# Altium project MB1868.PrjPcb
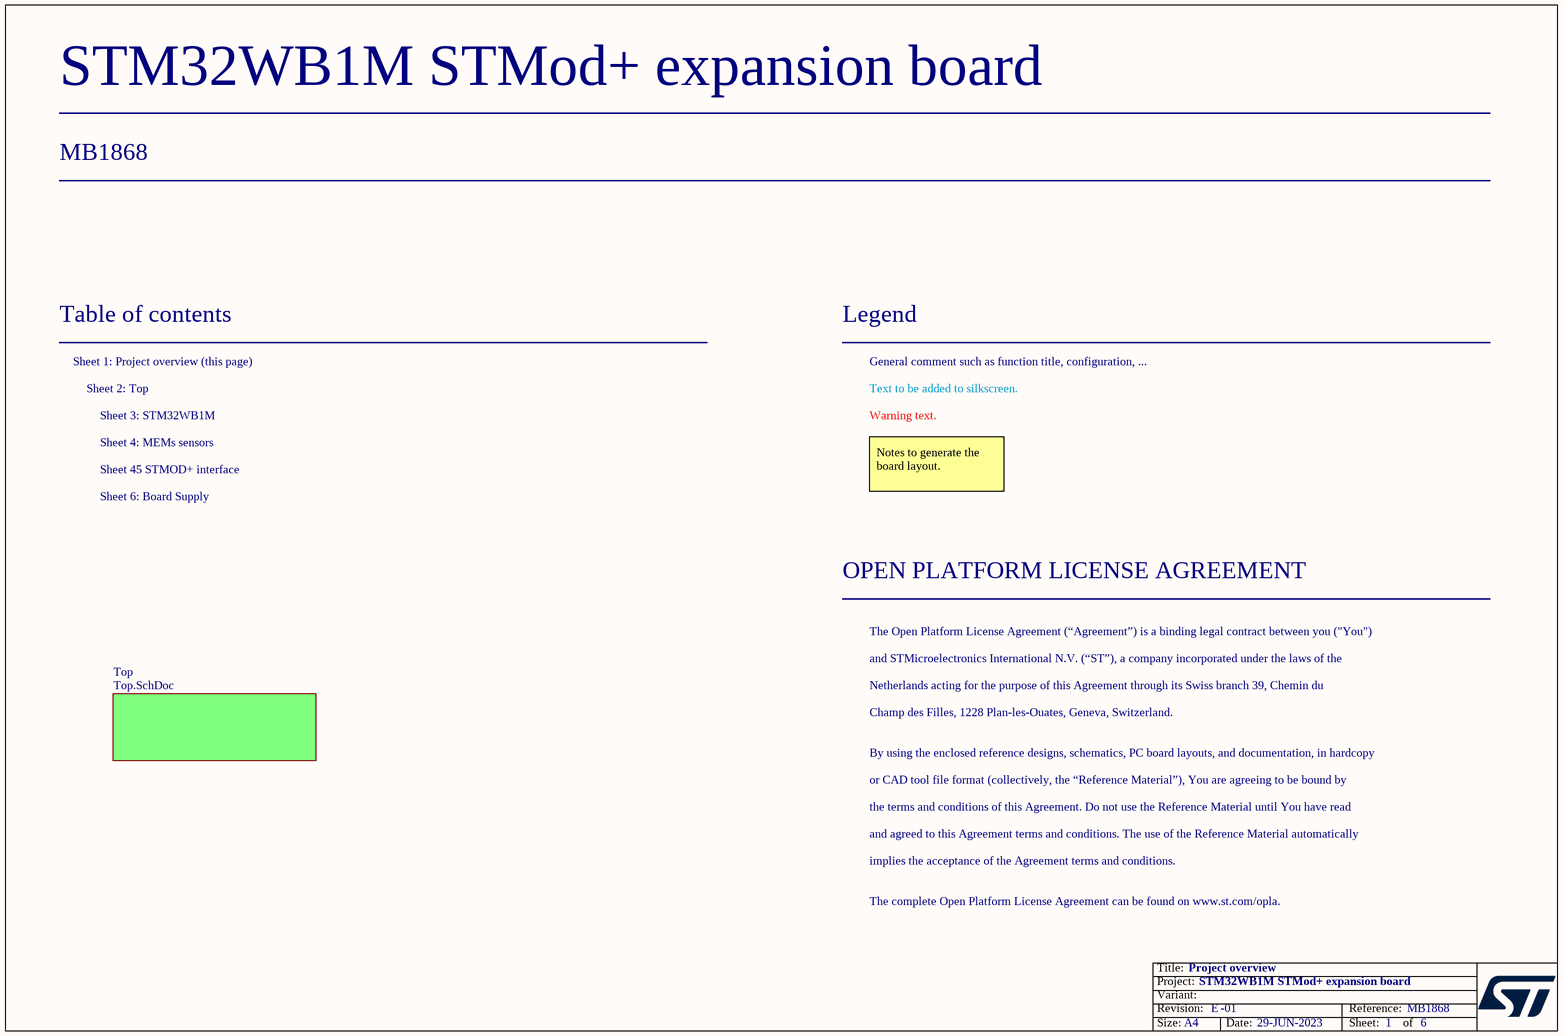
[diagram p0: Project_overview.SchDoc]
Board_Assembly_Revision: 01; Board_Document_Date: 29-JUN-2023; Board_Name: STM32WB1M STMod+ expansion board; Board_PCB_Revision: E; Board_Reference: MB1868
6 sheets, 72 parts. Net scope: flat (ports and power ports of the same name join across sheets).
Board file: MB1868.PcbDoc
Sheets:
  Project_overview.SchDoc
    Top = Top.SchDoc
      U_Mems = Mems.SchDoc
      U_STM32WB1M = STM32WB1M.SchDoc
      U_Board_supply = Board_supply.SchDoc
      U_STMOD+_interface = STMOD+_interface.SchDoc

## Sheet Project_overview.SchDoc: Project overview
size A4; Date: Not used; ApprovedBy: Not used; CheckedBy: Not used; Author: Not used; CompanyName: STMicroelectronics; DrawnBy: Not used; Engineer: Not used; Organization: Not used; Address1: Not used; Address2: Not used; Address3: Not used; Address4: Not used; DocumentNumber: Not used; Revision: Not used; SheetNumber: 1; SheetTotal: 6

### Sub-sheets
Top = Top.SchDoc: no entries

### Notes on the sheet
- Table of contents
- Sheet 1: Project overview (this page)
- Legend
- General comment such as function title, configuration, ...
- Sheet 2: Top
- Sheet 3: STM32WB1M
- Sheet 4: MEMs sensors
- Text to be added to silkscreen.
- Warning text.
- Sheet 6: Board Supply
- Sheet 45 STMOD+ interface
- Notes to generate the board layout.
- OPEN PLATFORM LICENSE AGREEMENT
- The Open Platform License Agreement (“Agreement”) is a binding legal contract between you ("You")
- and STMicroelectronics International N.V. (“ST”), a company incorporated under the laws of the
- Netherlands acting for the purpose of this Agreement through its Swiss branch 39, Chemin du
- Champ des Filles, 1228 Plan-les-Ouates, Geneva, Switzerland.
- By using the enclosed reference designs, schematics, PC board layouts, and documentation, in hardcopy
- or CAD tool file format (collectively, the “Reference Material”), You are agreeing to be bound by
- the terms and conditions of this Agreement. Do not use the Reference Material until You have read
- and agreed to this Agreement terms and conditions. The use of the Reference Material automatically
- implies the acceptance of the Agreement terms and conditions.
- The complete Open Platform License Agreement can be found on www.st.com/opla.

## Sheet Top.SchDoc: Top hierarchical view
size A4; Date: Not used; ApprovedBy: Not used; CheckedBy: Not used; Author: Not used; CompanyName: STMicroelectronics; DrawnBy: Not used; Engineer: Not used; Organization: Not used; Address1: Not used; Address2: Not used; Address3: Not used; Address4: Not used; DocumentNumber: Not used; Revision: Not used; SheetNumber: 2; SheetTotal: 6
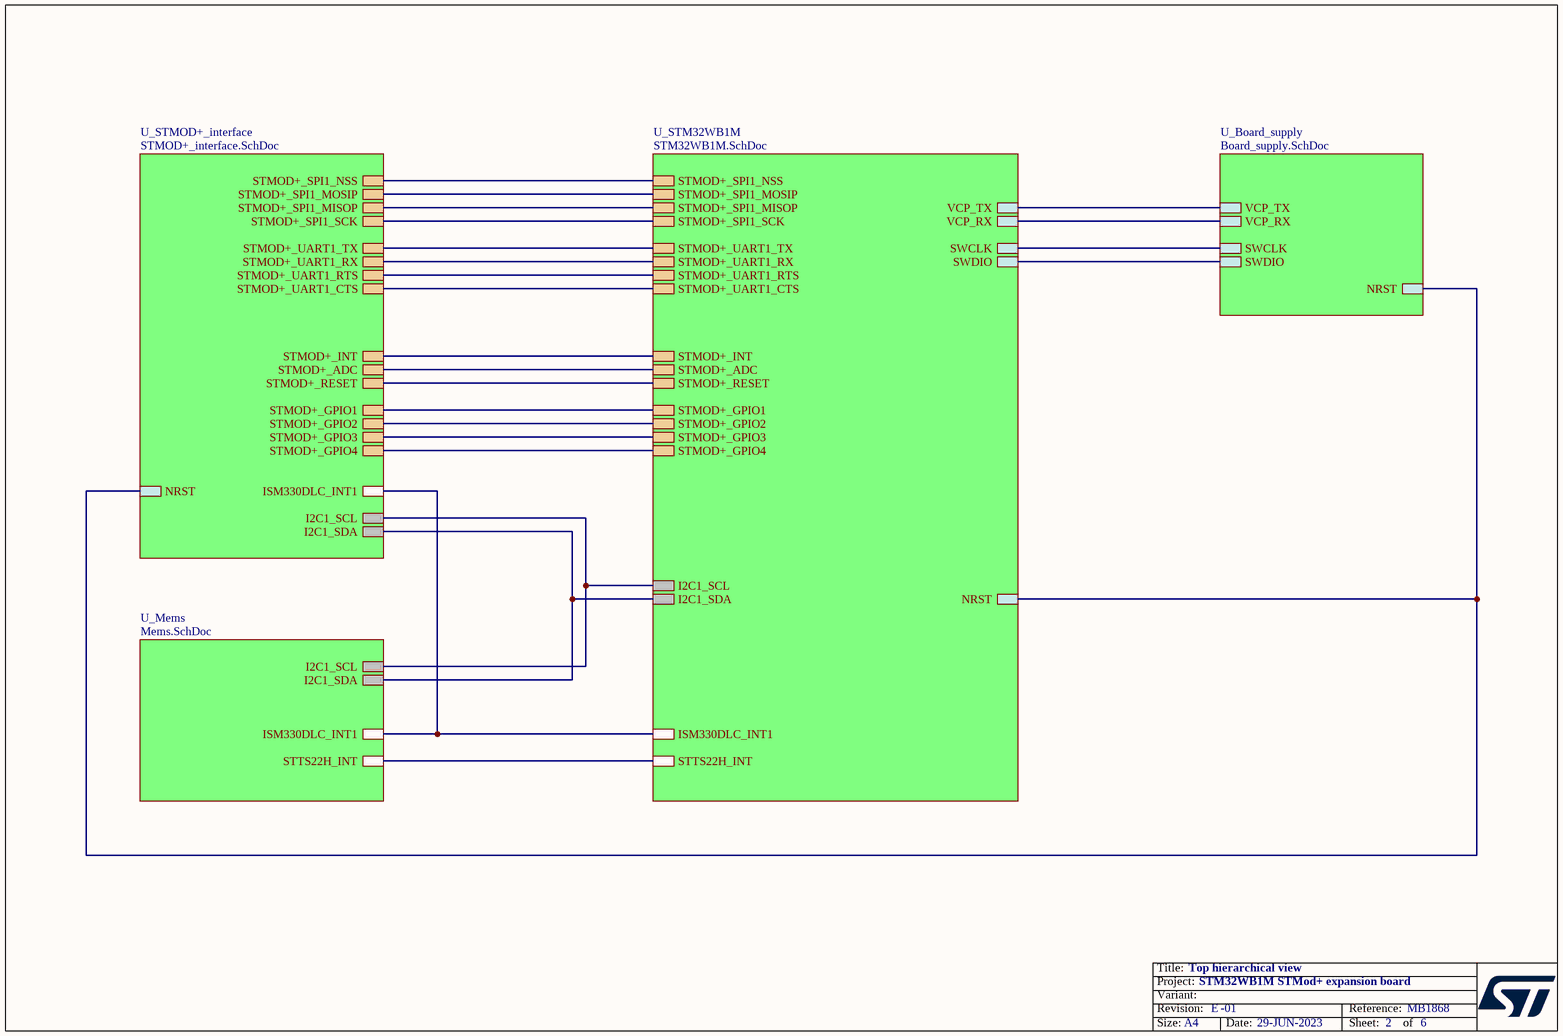
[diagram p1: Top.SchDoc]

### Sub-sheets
U_Board_supply = Board_supply.SchDoc: SWCLK, NRST, SWDIO, VCP_TX, VCP_RX
U_Mems = Mems.SchDoc: STTS22H_INT, ISM330DLC_INT1, I2C1_SCL, I2C1_SDA
U_STM32WB1M = STM32WB1M.SchDoc: VCP_TX, VCP_RX, SWCLK, SWDIO, ISM330DLC_INT1, STTS22H_INT, STMOD+_UART1_RX, STMOD+_UART1_TX, STMOD+_GPIO2, STMOD+_GPIO1, STMOD+_SPI1_SCK, STMOD+_SPI1_MOSIP, STMOD+_RESET, STMOD+_GPIO3, STMOD+_SPI1_NSS, STMOD+_UART1_RTS, STMOD+_INT, STMOD+_ADC, STMOD+_UART1_CTS, STMOD+_SPI1_MISOP, NRST, I2C1_SCL, I2C1_SDA, STMOD+_GPIO4
U_STMOD+_interface = STMOD+_interface.SchDoc: I2C1_SCL, I2C1_SDA, STMOD+_SPI1_MOSIP, STMOD+_UART1_TX, STMOD+_UART1_RX, STMOD+_SPI1_SCK, STMOD+_UART1_RTS, STMOD+_GPIO1, STMOD+_SPI1_NSS, STMOD+_INT, STMOD+_GPIO3, STMOD+_RESET, STMOD+_GPIO2, NRST, ISM330DLC_INT1, STMOD+_ADC, STMOD+_UART1_CTS, STMOD+_SPI1_MISOP, STMOD+_GPIO4

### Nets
(unnamed): sheet U_Mems/STTS22H_INT, sheet U_STM32WB1M/STTS22H_INT
(unnamed): sheet U_Mems/ISM330DLC_INT1, sheet U_STM32WB1M/ISM330DLC_INT1, sheet U_STMOD+_interface/ISM330DLC_INT1  [a separate net that carries the same name]
(unnamed): sheet U_Mems/I2C1_SCL, sheet U_STM32WB1M/I2C1_SCL, sheet U_STMOD+_interface/I2C1_SCL  [a separate net that carries the same name]
(unnamed): sheet U_Mems/I2C1_SDA, sheet U_STM32WB1M/I2C1_SDA, sheet U_STMOD+_interface/I2C1_SDA  [a separate net that carries the same name]
(unnamed): sheet U_STM32WB1M/VCP_TX, sheet U_Board_supply/VCP_TX  [a separate net that carries the same name]
(unnamed): sheet U_STM32WB1M/VCP_RX, sheet U_Board_supply/VCP_RX  [a separate net that carries the same name]
(unnamed): sheet U_STM32WB1M/SWCLK, sheet U_Board_supply/SWCLK  [a separate net that carries the same name]
(unnamed): sheet U_STM32WB1M/SWDIO, sheet U_Board_supply/SWDIO  [a separate net that carries the same name]
(unnamed): sheet U_STM32WB1M/STMOD+_UART1_RX, sheet U_STMOD+_interface/STMOD+_UART1_RX  [a separate net that carries the same name]
(unnamed): sheet U_STM32WB1M/STMOD+_UART1_TX, sheet U_STMOD+_interface/STMOD+_UART1_TX  [a separate net that carries the same name]
(unnamed): sheet U_STM32WB1M/STMOD+_GPIO2, sheet U_STMOD+_interface/STMOD+_GPIO2  [a separate net that carries the same name]
(unnamed): sheet U_STM32WB1M/STMOD+_GPIO1, sheet U_STMOD+_interface/STMOD+_GPIO1  [a separate net that carries the same name]
(unnamed): sheet U_STM32WB1M/STMOD+_SPI1_SCK, sheet U_STMOD+_interface/STMOD+_SPI1_SCK  [a separate net that carries the same name]
(unnamed): sheet U_STM32WB1M/STMOD+_SPI1_MOSIP, sheet U_STMOD+_interface/STMOD+_SPI1_MOSIP  [a separate net that carries the same name]
(unnamed): sheet U_STM32WB1M/STMOD+_RESET, sheet U_STMOD+_interface/STMOD+_RESET  [a separate net that carries the same name]
(unnamed): sheet U_STM32WB1M/STMOD+_GPIO3, sheet U_STMOD+_interface/STMOD+_GPIO3  [a separate net that carries the same name]
(unnamed): sheet U_STM32WB1M/STMOD+_SPI1_NSS, sheet U_STMOD+_interface/STMOD+_SPI1_NSS  [a separate net that carries the same name]
(unnamed): sheet U_STM32WB1M/STMOD+_UART1_RTS, sheet U_STMOD+_interface/STMOD+_UART1_RTS  [a separate net that carries the same name]
(unnamed): sheet U_STM32WB1M/STMOD+_INT, sheet U_STMOD+_interface/STMOD+_INT  [a separate net that carries the same name]
(unnamed): sheet U_STM32WB1M/STMOD+_ADC, sheet U_STMOD+_interface/STMOD+_ADC  [a separate net that carries the same name]
(unnamed): sheet U_STM32WB1M/STMOD+_UART1_CTS, sheet U_STMOD+_interface/STMOD+_UART1_CTS  [a separate net that carries the same name]
(unnamed): sheet U_STM32WB1M/STMOD+_SPI1_MISOP, sheet U_STMOD+_interface/STMOD+_SPI1_MISOP  [a separate net that carries the same name]
(unnamed): sheet U_STM32WB1M/NRST, sheet U_Board_supply/NRST, sheet U_STMOD+_interface/NRST  [a separate net that carries the same name]
(unnamed): sheet U_STM32WB1M/STMOD+_GPIO4, sheet U_STMOD+_interface/STMOD+_GPIO4  [a separate net that carries the same name]

## Sheet Mems.SchDoc: Mems Sensors
size A4; Date: Not used; ApprovedBy: Not used; CheckedBy: Not used; Author: Not used; CompanyName: STMicroelectronics; DrawnBy: Not used; Engineer: Not used; Organization: Not used; Address1: Not used; Address2: Not used; Address3: Not used; Address4: Not used; DocumentNumber: Not used; Revision: Not used; SheetNumber: 4; SheetTotal: 6
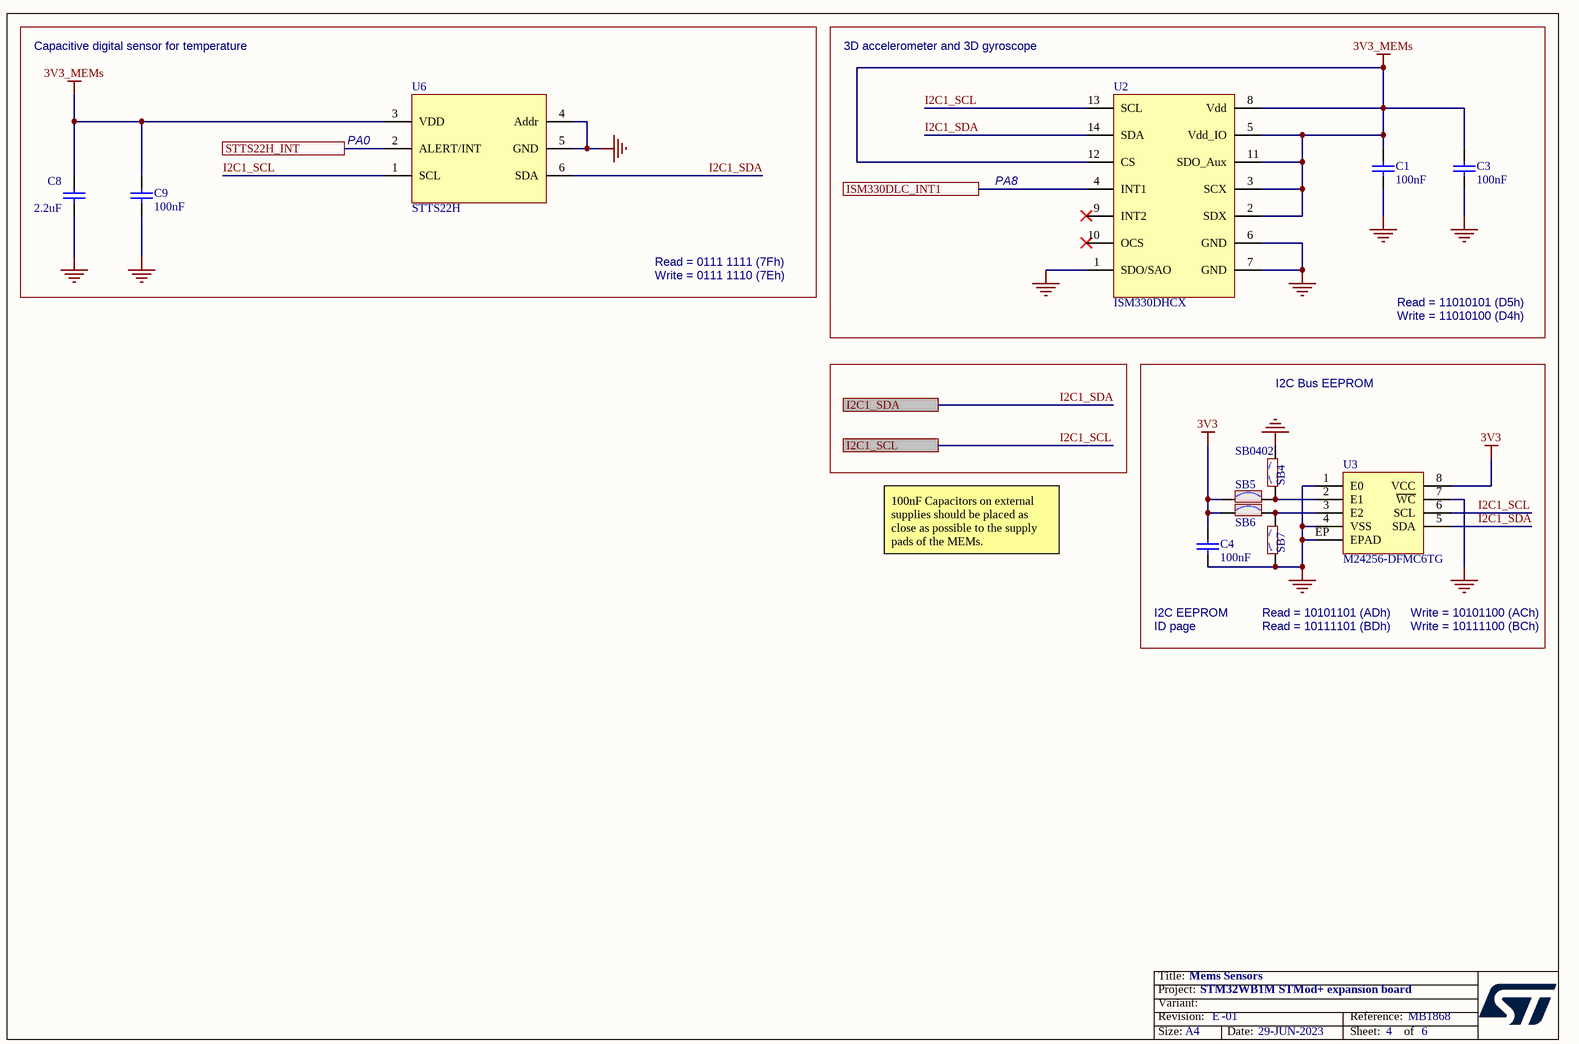
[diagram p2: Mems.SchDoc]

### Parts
C1  value 100nF  [C0402]  (hidden comment: Capacitor)
C3  value 100nF  [C0402]  (hidden comment: Capacitor)
C4  value 100nF  [C0402]  (hidden comment: Capacitor)
C8  value 2.2uF  [C0402]  (hidden comment: Capacitor)
C9  value 100nF  [C0402]  (hidden comment: Capacitor)
SB4  value SB0402  [SOLDER-BRIDGE_R0402-0R]  (hidden comment: SB_OFF)
SB5  SB_ON  [SOLDER-BRIDGE_R0402-0R]  (value not drawn)
SB6  SB_ON  [SOLDER-BRIDGE_R0402-0R]  (value not drawn)
SB7  SB_OFF  [SOLDER-BRIDGE_R0402-0R]  (value not drawn)
U2  ISM330DHCX  [ICC_LGA14_3X2P5_P050]
U3  value M24256-DFMC6TG  [ICC_DFN8-EPAD_2X3_P050]  (hidden comment: M24128-DFMC6TP)
U6  STTS22H  [ICC_UDFN6-EPAD_2X2_P065]

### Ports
I2C1_SCL, I2C1_SDA, ISM330DLC_INT1, STTS22H_INT

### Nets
3V3: C4.2 SB5.1 SB6.1 U3.8(VCC)
3V3_MEMs: C1.2 C3.2 C8.2 C9.2 U2.2(SDX) U2.3(SCX) U2.5(Vdd_IO) U2.8(Vdd) U2.11(SDO_Aux) U2.12(CS) U6.3(VDD)
GND: C1.1 C3.1 C4.1 C8.1 C9.1 SB4.1 SB7.2 U2.1(SDO/SAO) U2.6(GND) U2.7(GND) U3.1(E0) U3.4(VSS) U3.7(~{WC}) U3.EP(EPAD) U6.4(Addr) U6.5(GND)
I2C1_SCL: U2.13(SCL) U3.6(SCL) U6.1(SCL) ; port I2C1_SCL
I2C1_SDA: U2.14(SDA) U3.5(SDA) U6.6(SDA) ; port I2C1_SDA
PA0: U6.2(ALERT/INT) ; port STTS22H_INT
PA8: U2.4(INT1) ; port ISM330DLC_INT1
NetSB4_2: SB4.2 SB5.2 U3.2(E1)
NetSB6_2: SB6.2 SB7.1 U3.3(E2)

Not connected (* = marked no-connect by the designer): U2 9(INT2)* 10(OCS)*

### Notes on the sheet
- Capacitive digital sensor for temperature
- 3D accelerometer and 3D gyroscope
- (near U6) PA0
- PA8
- Read = 0111 1111 (7Fh)
- Write = 0111 1110 (7Eh)
- Read = 11010101 (D5h)
- Write = 11010100 (D4h)
- I2C Bus EEPROM
- 100nF Capacitors on external supplies should be placed as close as possible to the supply pads of the MEMs.
- I2C EEPROM
- ID page
- Read = 10101101 (ADh)
- Read = 10111101 (BDh)
- Write = 10101100 (ACh)
- Write = 10111100 (BCh)

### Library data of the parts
C1 C3 C4 C9 = MCD-00006: Capacitor, MLCC, 100nF, 16V, X7R, +/-10%, 0402, T=0.5mm; Part_Preference: Recommended; Manufacturer: YAGEO; Manufacturer_Part_Number: CC0402KRX7R7BB104; Partial_Alternate_Internal_Part_Number: MCD-03299; Order_Code_RS: 616-9701; Component_Country_Of_Origin: China; ShowFields: YES; ID: 2474
C8 = MCD-01823: Capacitor, MLCC, 2.2uF, 6V3, X5R,+/-10%, 0402, T=0.5mm; Manufacturer_Part_Number: GRM155R60J225KE95D; Manufacturer: MURATA; Part_Preference: Recommended; Order_Code_RS: 172-6478
SB4 = MCD-02162: Solder Bridge 0402 OFF; Part_Type: Misc; Part_Preference: Recommended; Manufacturer: YAGEO; Manufacturer_Part_Number: RC0402JR-070RL; Order_Code_RS: 618-5804; Component_Country_Of_Origin: China; ShowFields: YES; ID: 4262
SB5 SB6 = MCD-01618: Solder Bridge 0402 ON; Part_Type: Misc; Manufacturer_Part_Number: RC0402JR-070RL; Manufacturer: YAGEO; Part_Preference: Recommended; Order_Code_RS: 618-5804; Value: 0 ohm; Component_Country_Of_Origin: China; ShowFields: YES; ID: 3718
SB7 = MCD-02162: Solder Bridge 0402 OFF; Part_Type: Misc; Part_Preference: Recommended; Manufacturer: YAGEO; Manufacturer_Part_Number: RC0402JR-070RL; Order_Code_RS: 618-5804; Value: SB0402; Component_Country_Of_Origin: China; ShowFields: YES; ID: 4262
U2 = MCD-02160: iNEMO inertial module: 3D accelerometer and 3D gyroscope, with digital output for industrial applications; Part_Type: IC; Part_Preference: Recommended; Manufacturer: STMICROELECTRONICS; Manufacturer_HQ_COO: EU; Order_code_RS: ISM330DHCXTR; Component_Country_Of_Origin: Malta, Philippines
U3 = MCD-01871: I2C Memory 3V3, 256Kbits, 2x3,0.55mm, UFDFPN8; Part_Type: IC; Manufacturer: STMICROELECTRONICS; BMS_Part_Number: 9175665; Part_Preference: Recommended; Manufacturer_HQ_COO: EU
U6 = MCD-02159: temperature sensor; Part_Type: IC; Part_Preference: Recommended; Manufacturer: STMICROELECTRONICS; Manufacturer_HQ_COO: EU; Order_code_RS: 194-7646; Component_Country_Of_Origin: Thailand

## Sheet STM32WB1M.SchDoc: STM32WB1M
size A4; Date: Not used; ApprovedBy: Not used; CheckedBy: Not used; Author: Not used; CompanyName: STMicroelectronics; DrawnBy: Not used; Engineer: Not used; Organization: Not used; Address1: Not used; Address2: Not used; Address3: Not used; Address4: Not used; DocumentNumber: Not used; Revision: Not used; SheetNumber: 3; SheetTotal: 6
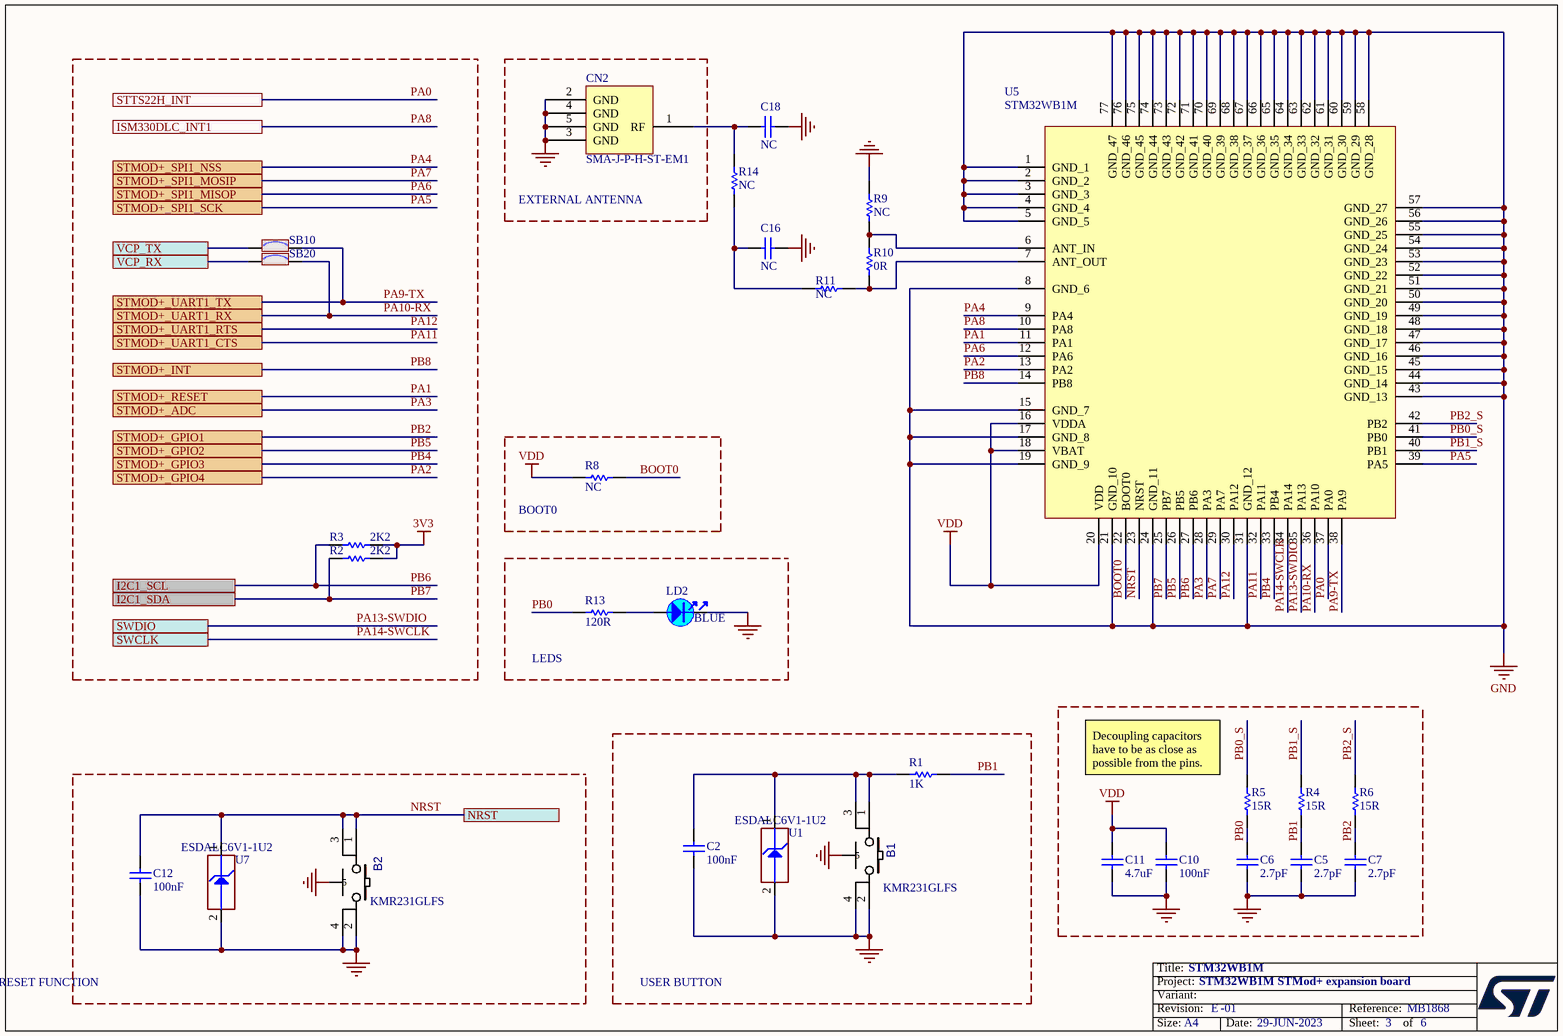
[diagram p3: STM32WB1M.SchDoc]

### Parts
B1  value KMR231GLFS  [SWI_C&K_Y78B23110FP__ITT_KMR231GLFS]
B2  value KMR231GLFS  [SWI_C&K_Y78B23110FP__ITT_KMR231GLFS]
C2  value 100nF  [C0402]  (hidden comment: Capacitor)
C5  value 2.7pF  [C0201_H0P3]  (hidden comment: Capacitor)
C6  value 2.7pF  [C0201_H0P3]  (hidden comment: Capacitor)
C7  value 2.7pF  [C0201_H0P3]  (hidden comment: Capacitor)
C10  value 100nF  [C0402]  (hidden comment: Capacitor)
C11  value 4.7uF  [C0603]
C12  value 100nF  [C0402]  (hidden comment: Capacitor)
C16  value NC  [C0402]  (hidden comment: Capacitor)
C18  value NC  [C0402]  (hidden comment: Capacitor)
CN2  value SMA-J-P-H-ST-EM1  [CON_SAMTEC_SMA-J-P-X-ST-EM1]
LD2  value BLUE  [LED_0603_OSRAM_LB-Q39G-L2OO-35-1_BLUE_1A2K_H0P4]
R1  value 1K  [R0402]
R2  value 2K2  [R0402]  (hidden comment: Resistor)
R3  value 2K2  [R0402]  (hidden comment: Resistor)
R4  value 15R  [R0201_H0P23]  (hidden comment: Resistor)
R5  value 15R  [R0201_H0P23]  (hidden comment: Resistor)
R6  value 15R  [R0201_H0P23]  (hidden comment: Resistor)
R8  value NC  [R0402]
R9  value NC  [R0201_H0P23]  (hidden comment: Resistor)
R10  value 0R  [R0201_H0P23]  (hidden comment: Resistor)
R11  value NC  [R0201_H0P23]  (hidden comment: Resistor)
R13  value 120R  [R0402]
R14  value NC  [R0402]  (hidden comment: Resistor)
SB10  SB_ON  [SOLDER-BRIDGE_R0402-0R]  (value not drawn)
SB20  SB_ON  [SOLDER-BRIDGE_R0402-0R]  (value not drawn)
U1  value ESDALC6V1-1U2  [ESD_ST0201]
U5  STM32WB1M  [ICC_LBA77_6P5X10_P0P45]
U7  value ESDALC6V1-1U2  [ESD_ST0201]

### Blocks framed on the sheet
EXTERNAL ANTENNA: CN2
BOOT0: R8
LEDS: LD2 R13
USER BUTTON: B1 C2 R1 U1
RESET FUNCTION: B2 C12 U7

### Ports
I2C1_SCL, I2C1_SDA, ISM330DLC_INT1, NRST, STMOD+_ADC, STMOD+_GPIO1, STMOD+_GPIO2, STMOD+_GPIO3, STMOD+_GPIO4, STMOD+_INT, STMOD+_RESET, STMOD+_SPI1_MISOP, STMOD+_SPI1_MOSIP, STMOD+_SPI1_NSS, STMOD+_SPI1_SCK, STMOD+_UART1_CTS, STMOD+_UART1_RTS, STMOD+_UART1_RX, STMOD+_UART1_TX, STTS22H_INT, SWCLK, SWDIO, VCP_RX, VCP_TX

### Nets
3V3: R2.2 R3.2
GND: B1.2 B1.4 B1.5 B2.2 B2.4 B2.5 C2.1 C5.1 C6.1 C7.1 C10.1 C11.1 C12.1 C16.2 C18.2 CN2.2(GND) CN2.3(GND) CN2.4(GND) CN2.5(GND) LD2.2 R9.2 U1.2(GND) U5.1(GND_1) U5.2(GND_2) U5.3(GND_3) U5.4(GND_4) U5.5(GND_5) U5.8(GND_6) U5.15(GND_7) U5.17(GND_8) U5.19(GND_9) U5.21(GND_10) U5.24(GND_11) U5.31(GND_12) U5.43(GND_13) U5.44(GND_14) U5.45(GND_15) U5.46(GND_16) U5.47(GND_17) U5.48(GND_18) U5.49(GND_19) U5.50(GND_20) U5.51(GND_21) U5.52(GND_22) U5.53(GND_23) U5.54(GND_24) U5.55(GND_25) U5.56(GND_26) U5.57(GND_27) U5.58(GND_28) U5.59(GND_29) U5.60(GND_30) U5.61(GND_31) U5.62(GND_32) U5.63(GND_33) U5.64(GND_34) U5.65(GND_35) U5.66(GND_36) U5.67(GND_37) U5.68(GND_38) U5.69(GND_39) U5.70(GND_40) U5.71(GND_41) U5.72(GND_42) U5.73(GND_43) U5.74(GND_44) U5.75(GND_45) U5.76(GND_46) U5.77(GND_47) U7.2(GND)
VDD: C10.2 C11.2 R8.1 U5.16(VDDA) U5.18(VBAT) U5.20(VDD)
BOOT0: R8.2 U5.22(BOOT0)
NRST: B2.1 B2.3 C12.2 U5.23(NRST) U7.1(IO1) ; port NRST
PA0: U5.37(PA0) ; port STTS22H_INT
PA1: U5.11(PA1) ; port STMOD+_RESET
PA2: U5.13(PA2) ; port STMOD+_GPIO4
PA3: U5.28(PA3) ; port STMOD+_ADC
PA4: U5.9(PA4) ; port STMOD+_SPI1_NSS
PA5: U5.39(PA5) ; port STMOD+_SPI1_SCK
PA6: U5.12(PA6) ; port STMOD+_SPI1_MISOP
PA7: U5.29(PA7) ; port STMOD+_SPI1_MOSIP
PA8: U5.10(PA8) ; port ISM330DLC_INT1
PA9-TX: SB10.2 U5.38(PA9) ; port STMOD+_UART1_TX
PA10-RX: SB20.2 U5.36(PA10) ; port STMOD+_UART1_RX
PA11: U5.32(PA11) ; port STMOD+_UART1_CTS
PA12: U5.30(PA12) ; port STMOD+_UART1_RTS
PA13-SWDIO: U5.35(PA13) ; port SWDIO
PA14-SWCLK: U5.34(PA14) ; port SWCLK
PB0: C6.2 R5.1 R13.1
PB0_S: R5.2 U5.41(PB0)
PB1: C5.2 R1.2 R4.1
PB1_S: R4.2 U5.40(PB1)
PB2: C7.2 R6.1 ; port STMOD+_GPIO1
PB2_S: R6.2 U5.42(PB2)
PB4: U5.33(PB4) ; port STMOD+_GPIO3
PB5: U5.26(PB5) ; port STMOD+_GPIO2
PB6: R3.1 U5.27(PB6) ; port I2C1_SCL  [project net I2C1_SCL]
PB7: R2.1 U5.25(PB7) ; port I2C1_SDA  [project net I2C1_SDA]
PB8: U5.14(PB8) ; port STMOD+_INT
VCP_RX: SB20.1 ; port VCP_RX
VCP_TX: SB10.1 ; port VCP_TX
NetB1_1: B1.1 B1.3 C2.2 R1.1 U1.1(IO1)
NetC16_1: C16.1 R11.1 R14.1
NetC18_1: C18.1 CN2.1(RF) R14.2
NetLD2_1: LD2.1 R13.2
NetR9_1: R9.1 R10.2 U5.6(ANT_IN)
NetR10_1: R10.1 R11.2 U5.7(ANT_OUT)

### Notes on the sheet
- (near R5) Decoupling capacitors have to be as close as possible from the pins.

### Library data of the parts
B1 B2 = MCD-01485: Microminiature Tact Switch for SMT - KMR 2 Series - 1.9 mm height; Part_Type: Misc; Manufacturer: C&K; Provided_By: SUBCO
C2 C10 C12 = MCD-00006: as C1 on sheet Mems
C5-C7 = MCD-0228?: Capacitor, MLCC, 2.7pF, 50V, NPO, +-0.05pF, 0201, T=0.3mm".; Internal_Part_Number: MCD-03603; Part_Preference: Recommended; Manufacturer: MURATA; Manufacturer_Part_Number: GRM0335C1H2R7BA01D; Component_Country_Of_Origin: Japan; ShowFields: YES
C11 = MCD-00009: Capacitor, MLCC, 4.7uF, 16V, X5R, 10%, 0603, T=0.8mm; Manufacturer_Part_Number: CC0603KRX5R7BB475; Manufacturer: YAGEO; Provided_By: SUBCO
C16 C18 = MCD-01995: Capacitor, MLCC, 22pF, 50V, C0G, +/-5%, 0402, T=0.5mm; Part_Preference: Recommended; Manufacturer: TDK; Manufacturer_Part_Number: C1005NP01H220J050BA
CN2 = MCD-00279: RF SMA connector PCB edge; Manufacturer: SAMTEC; Provided_By: SUBCO
LD2 = MCD-00585: LED Blue, 0603 SMD, Forward Voltage Min=2,8V, Max=3,8V; Part_Type: Display; Manufacturer_Part_Number: LB Q39G-L2OO-35-1; Manufacturer: OSRAM OPTO SEMICONDUCTORS; Order_Code_RS: 9148643; Provided_By: SUBCO
R1 = MCD-00061: Resistor,1K,0402,1%,1/16W; Manufacturer_Part_Number: RC0402FR-071KL; Manufacturer: YAGEO; Provided_By: SUBCO
R2 R3 = MCD-00057: Resistor, 2K2, 0402, +/-1%, 1/16W; Part_Preference: Recommended; Manufacturer: YAGEO; Manufacturer_Part_Number: RC0402FR-072K2L; Component_Country_Of_Origin: China; ShowFields: YES; ID: 2534
R4-R6 = MCD-03509: Resistor, 15R, 0201, 1%, 1/20W; Part_Preference: Recommended; Manufacturer: YAGEO; Manufacturer_Part_Number: RC0201FR-0715RL; Component_Country_Of_Origin: China; ShowFields: YES; ID: 5625
R8 R13 = MCD-00194: Resistor,120R,0402,1%,1/16W; Manufacturer_Part_Number: RC0402FR-07120RL; Manufacturer: YAGEO; Provided_By: SUBCO
R9 R11 = MCD-02253: Resistor, 0R, 0201, +/-1%, 1/20W; Part_Preference: Recommended; Manufacturer: YAGEO; Manufacturer_Part_Number: RC0201FR-070RL
R10 = MCD-02450: Resistor, 0R, 0201, 1/20W; Part_Preference: Recommended; Manufacturer: YAGEO; Manufacturer_Part_Number: RC0201JR-070RP; Component_Country_Of_Origin: China; ShowFields: YES; ID: 4556
R14 = MCD-02253: Resistor, 0R, 0402, +/-1%, 1/16W; Part_Preference: Recommended; Manufacturer: YAGEO; Manufacturer_Part_Number: RC0402JR-070RL
SB10 SB20 = MCD-01618: Solder Bridge 0402 ON; Part_Type: Misc; Part_Preference: Recommended; Manufacturer: YAGEO; Manufacturer_Part_Number: RC0402JR-070RL; Order_Code_RS: 618-5804
U1 U7 = MCD-00170: ESD protection 6V1; Part_Type: Diode; Manufacturer: STMICROELECTRONICS; BMS_Part_Number: 9151132; Provided_By: SUBCO with ST control
U5 = MCD-02528: STM32 BLE module based on STM32WB15; Part_Type: Misc; Part_Preference: Recommended; Manufacturer: STMICROELECTRONICS

## Sheet Board_supply.SchDoc: Board Supply
size A4; Date: Not used; ApprovedBy: Not used; CheckedBy: Not used; CompanyName: STMicroelectronics; DrawnBy: Not used; Engineer: Not used; Organization: Not used; Address1: Not used; Address2: Not used; Address3: Not used; Address4: Not used; DocumentNumber: Not used; Revision: Not used; SheetNumber: 6; SheetTotal: 6
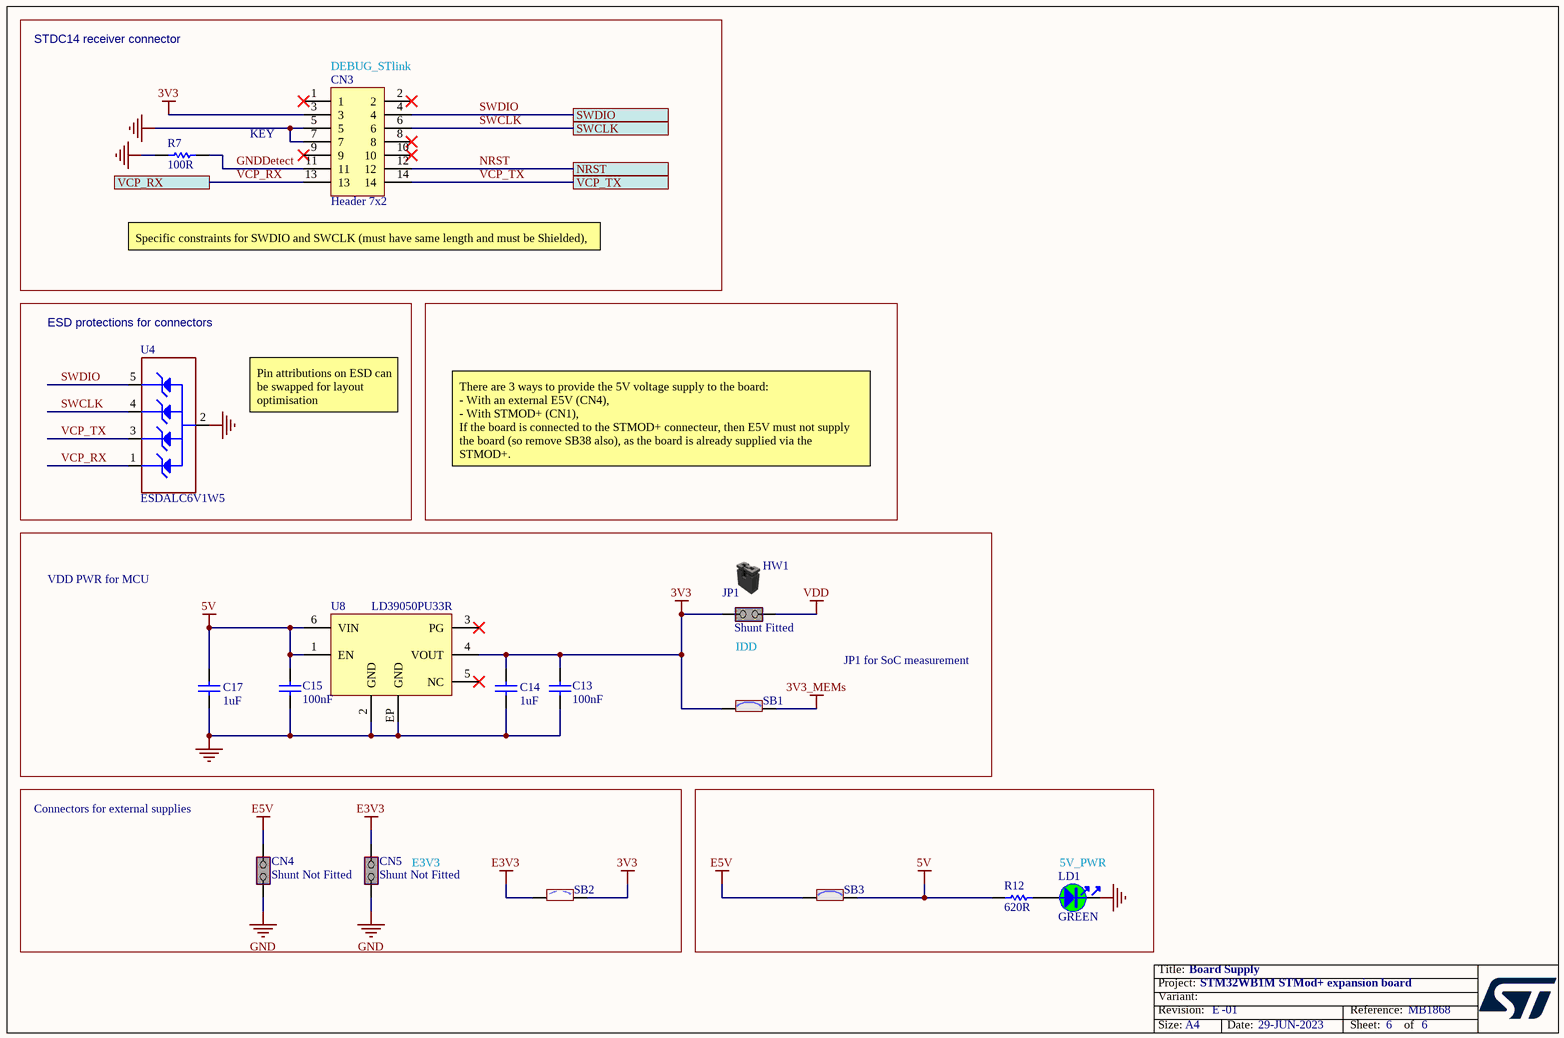
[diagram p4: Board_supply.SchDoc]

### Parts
C13  value 100nF  [C0402]  (hidden comment: Capacitor)
C14  value 1uF  [C0603]
C15  value 100nF  [C0402]  (hidden comment: Capacitor)
C17  value 1uF  [C0603]
CN3  Header 7x2  [CON_STDC14_Receiver_SMALL]
CN4  value Shunt Not Fitted  [CON_SAMTEC_TSW-102-07-G-S]
CN5  value Shunt Not Fitted  [CON_SAMTEC_TSW-102-07-G-S]
HW1  (no value)  (mechanical)
JP1  value Shunt Fitted  [CON_SAMTEC_TSW-102-07-G-S]
LD1  value GREEN  [LED_0603_OSRAM_LG-Q396-PS-35_GREEN_1A2K_H0P4]
R7  value 100R  [R0402]  (hidden comment: Resistor)
R12  value 620R  [R0402]
SB1  SB_ON  [SOLDER-BRIDGE_R0402-0R]  (value not drawn)
SB2  SB_OFF  [SOLDER-BRIDGE_R0402-0R]  (value not drawn)
SB3  SB_ON  [SOLDER-BRIDGE_R0402-0R]  (value not drawn)
U4  value ESDALC6V1W5  [ESD_SOT323-5L]
U8  value LD39050PU33R  [ICC_DFN6-EPAD_3X3_P095]

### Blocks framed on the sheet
ESD protections for connectors: U4
5V_PWR: LD1 R12 SB3

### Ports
NRST, SWCLK, SWDIO, VCP_RX, VCP_TX

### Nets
3V3: C13.2 C14.2 CN3.3 JP1.1(COMMON) SB1.1 SB2.2 U8.4(VOUT)
3V3_MEMs: SB1.2
5V: C15.2 C17.2 R12.1 SB3.2 U8.1(EN) U8.6(VIN)
E3V3: CN5.2(NO) SB2.1
E5V: CN4.2(NO) SB3.1
GND: C13.1 C14.1 C15.1 C17.1 CN3.5 CN3.7 CN4.1(COMMON) CN5.1(COMMON) LD1.2 R7.1 U4.2(GND) U8.2(GND) U8.EP(GND)
VDD: JP1.2(NO)
GNDDetect: CN3.11 R7.2
NRST: CN3.12 ; port NRST
SWCLK: CN3.6 U4.4(IO3) ; port SWCLK  [project net PA14-SWCLK]
SWDIO: CN3.4 U4.5(IO4) ; port SWDIO  [project net PA13-SWDIO]
VCP_RX: CN3.13 U4.1(IO1) ; port VCP_RX
VCP_TX: CN3.14 U4.3(IO2) ; port VCP_TX
NetLD1_1: LD1.1 R12.2

Not connected (* = marked no-connect by the designer): CN3 1* 2* 8* 9* 10*; U8 3(PG)* 5(NC)*

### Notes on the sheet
- STDC14 receiver connector
- (near CN3) DEBUG_STlink
- KEY
- (near CN3) Specific constraints for SWDIO and SWCLK (must have same length and must be Shielded),
- Pin attributions on ESD can be swapped for layout optimisation
- There are 3 ways to provide the 5V voltage supply to the board:
  - With an external E5V (CN4),
  - With STMOD+ (CN1),
  If the board is connected to the STMOD+ connecteur, then E5V must not supply the board (so remove SB38 also), as the board is already supplied via the STMOD+.
- VDD PWR for MCU
- (near JP1) IDD
- JP1 for SoC measurement
- Connectors for external supplies
- (near CN5) E3V3

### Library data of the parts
C13 C15 = MCD-00006: as C1 on sheet Mems
C14 C17 = MCD-00010: Capacitor, MLCC, 1uF, 16V, X5R, 10%, 0603, T=0,8mm; Manufacturer_Part_Number: CC0603KRX5R7BB105; Manufacturer: YAGEO; Provided_By: SUBCO
CN3 = MCD-00639: Header, 7x2, 1.27mm, VR, SMD, T=5.97mm; Part_Type: Connector; Part_Preference: Recommended; Manufacturer: SAMTEC; Manufacturer_Part_Number: FTSH-107-01-L-DV-K; Order_Code_RS: 179-8765
CN4 CN5 JP1 = MCD-00683: Header, 2x1, 2,54mm, VR, TH, Height 5.84mm/2.54mm - Shunt Fitted by default; Part_Type: Connector; Manufacturer_Part_Number: TSW-102-07-x-S; Manufacturer: SAMTEC; Provided_By: SUBCO
HW1 = MCD-00043: SHUNT 2.54mm BLACK; Manufacturer_Part_Number: SNT-100-BK-G; Manufacturer: SAMTEC; Part_Type: Mechanical; Provided_By: SUBCO; Value: SNT-100-BK-G
LD1 = MCD-00588: LED Green, 0603 SMD, Forward Voltage Typ=2V, Max=2.5V; Part_Type: Display; Manufacturer_Part_Number: LG Q396-PS-35; Manufacturer: OSRAM OPTO SEMICONDUCTORS; Alternate_Manufacturer_Part_Number: VLMTG1300-GS08; Alternate_Manufacturer: VISHAY SEMICONDUCTOR OPTO DIVISION; Provided_By: SUBCO
R7 = MCD-00067: Resistor, 100R, 0402, +/- 1%, 1/16W; Part_Preference: Recommended; Manufacturer: YAGEO; Manufacturer_Part_Number: RC0402FR-07100RL; Component_Country_Of_Origin: China; ShowFields: YES; ID: 2527
R12 = MCD-00499: Resistor,620R,0402,1%,1/16W; Manufacturer_Part_Number: RC0402FR-07620RL; Manufacturer: YAGEO; Provided_By: SUBCO
SB1 SB3 = MCD-01618: as SB10 on sheet STM32WB1M
SB2 = MCD-02162: Solder Bridge 0402 OFF; Part_Type: Misc; Part_Preference: Recommended; Manufacturer: YAGEO; Manufacturer_Part_Number: RC0402JR-070RL; Order_Code_RS: 618-5804
U4 = MCD-00136: Dual Transil array for ESD protection; Part_Type: Diode; Manufacturer: STMICROELECTRONICS; BMS_Part_Number: 9151112; Provided_By: SUBCO with ST control
U8 = MCD-00215: Low quiescent current and low noise voltage regulators; Manufacturer: STMICROELECTRONICS; Part_Type: IC; BMS_Part_Number: 9176126; Provided_By: SUBCO with ST control

## Sheet STMOD+_interface.SchDoc: STMOD+ interface
size A4; Date: Not used; ApprovedBy: Not used; CheckedBy: Not used; Author: Not used; CompanyName: STMicroelectronics; DrawnBy: Not used; Engineer: Not used; Organization: Not used; Address1: Not used; Address2: Not used; Address3: Not used; Address4: Not used; DocumentNumber: Not used; Revision: Not used; SheetNumber: 5; SheetTotal: 6
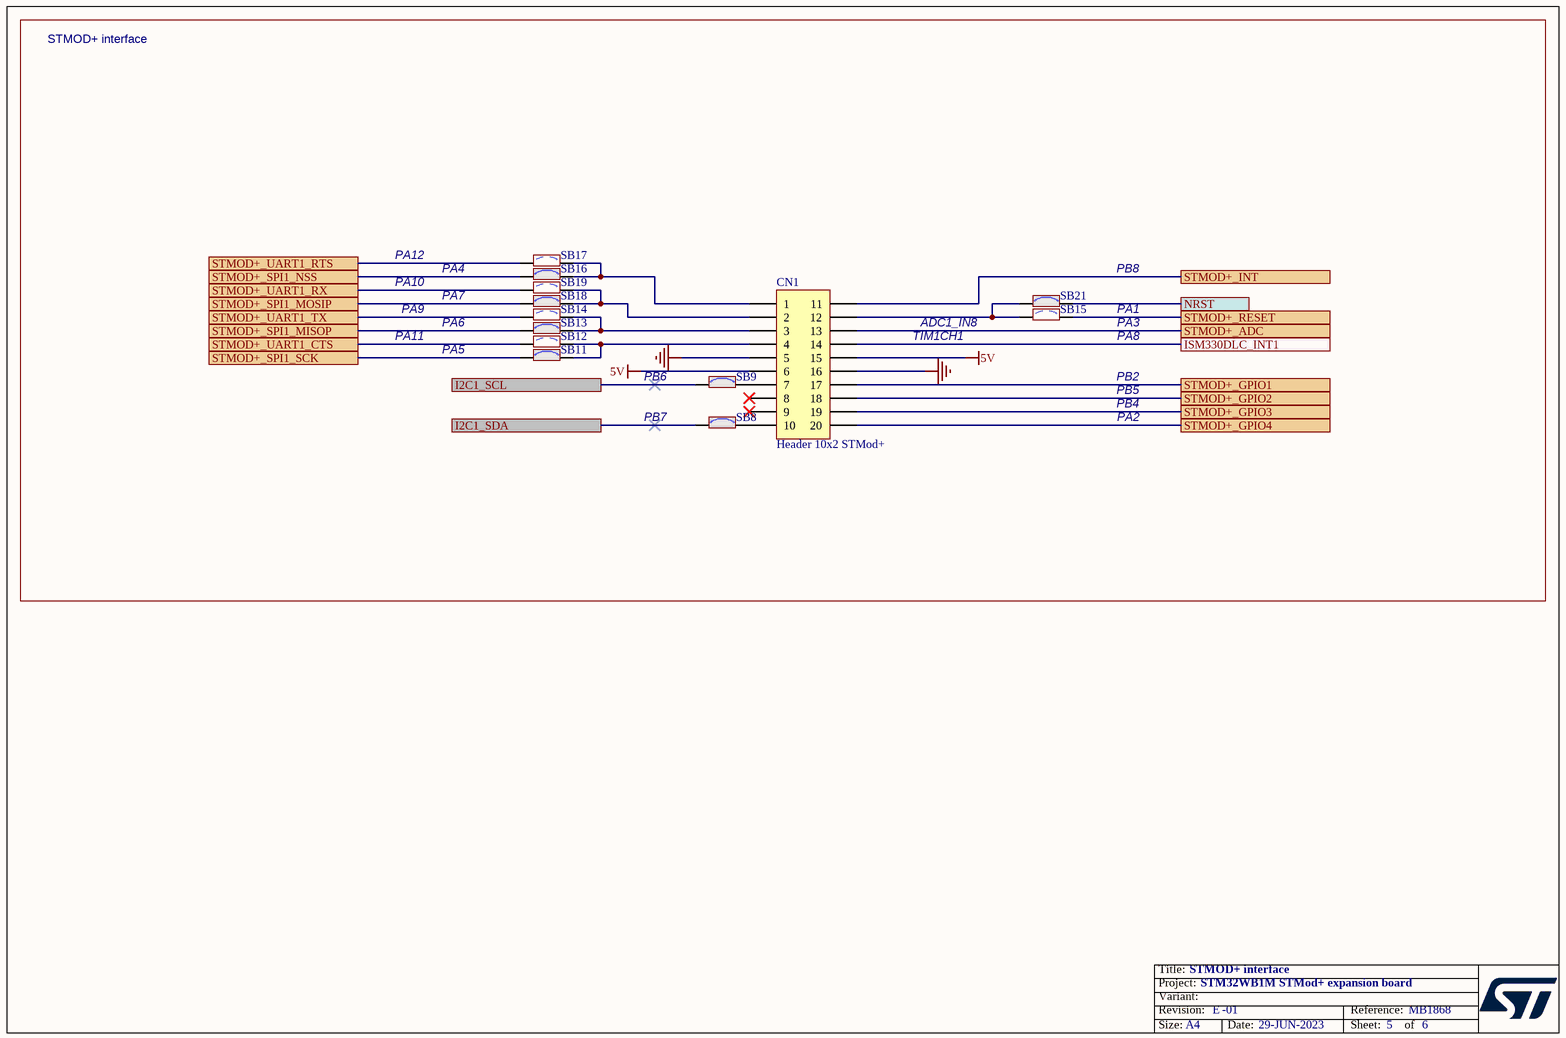
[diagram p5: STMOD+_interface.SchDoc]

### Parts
CN1  Header 10x2 STMod+  [CON_SAMTEC_TMM-110-01-L-D-RA__STMOD+]
SB8  SB_ON  [SOLDER-BRIDGE_R0402-0R]  (value not drawn)
SB9  SB_ON  [SOLDER-BRIDGE_R0402-0R]  (value not drawn)
SB11  SB_ON  [SOLDER-BRIDGE_R0402-0R]  (value not drawn)
SB12  SB_OFF  [SOLDER-BRIDGE_R0402-0R]  (value not drawn)
SB13  SB_ON  [SOLDER-BRIDGE_R0402-0R]  (value not drawn)
SB14  SB_OFF  [SOLDER-BRIDGE_R0402-0R]  (value not drawn)
SB15  SB_OFF  [SOLDER-BRIDGE_R0402-0R]  (value not drawn)
SB16  SB_ON  [SOLDER-BRIDGE_R0402-0R]  (value not drawn)
SB17  SB_OFF  [SOLDER-BRIDGE_R0402-0R]  (value not drawn)
SB18  SB_ON  [SOLDER-BRIDGE_R0402-0R]  (value not drawn)
SB19  SB_OFF  [SOLDER-BRIDGE_R0402-0R]  (value not drawn)
SB21  SB_ON  [SOLDER-BRIDGE_R0402-0R]  (value not drawn)

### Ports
I2C1_SCL, I2C1_SDA, ISM330DLC_INT1, NRST, STMOD+_ADC, STMOD+_GPIO1, STMOD+_GPIO2, STMOD+_GPIO3, STMOD+_GPIO4, STMOD+_INT, STMOD+_RESET, STMOD+_SPI1_MISOP, STMOD+_SPI1_MOSIP, STMOD+_SPI1_NSS, STMOD+_SPI1_SCK, STMOD+_UART1_CTS, STMOD+_UART1_RTS, STMOD+_UART1_RX, STMOD+_UART1_TX

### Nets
5V: CN1.6 CN1.15
GND: CN1.5 CN1.16
I2C1_SCL: SB9.1 ; port I2C1_SCL
I2C1_SDA: SB8.1 ; port I2C1_SDA
NRST: SB21.2 ; port NRST
PA1: SB15.2 ; port STMOD+_RESET
PA2: CN1.20 ; port STMOD+_GPIO4
PA3: CN1.13 ; port STMOD+_ADC
PA4: SB16.1 ; port STMOD+_SPI1_NSS
PA5: SB11.1 ; port STMOD+_SPI1_SCK
PA6: SB13.1 ; port STMOD+_SPI1_MISOP
PA7: SB18.1 ; port STMOD+_SPI1_MOSIP
PA8: CN1.14 ; port ISM330DLC_INT1
PA9-TX: SB14.1 ; port STMOD+_UART1_TX
PA10-RX: SB19.1 ; port STMOD+_UART1_RX
PA11: SB12.1 ; port STMOD+_UART1_CTS
PA12: SB17.1 ; port STMOD+_UART1_RTS
PB2: CN1.17 ; port STMOD+_GPIO1
PB4: CN1.19 ; port STMOD+_GPIO3
PB5: CN1.18 ; port STMOD+_GPIO2
PB8: CN1.11 ; port STMOD+_INT
NetCN1_1: CN1.1 SB16.2 SB17.2
NetCN1_2: CN1.2 SB18.2 SB19.2
NetCN1_3: CN1.3 SB13.2 SB14.2
NetCN1_4: CN1.4 SB11.2 SB12.2
NetCN1_7: CN1.7 SB9.2
NetCN1_10: CN1.10 SB8.2
NetCN1_12: CN1.12 SB15.1 SB21.1

Not connected (* = marked no-connect by the designer): CN1 8* 9*

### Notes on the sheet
- STMOD+ interface
- PA9
- PA12
- PA10
- PA7
- PA4
- PA1
- PB8
- PA11
- PA6
- PA5
- PB6
- TIM1CH1
- ADC1_IN8
- PA8
- PA3
- PB2
- PB7
- PB4
- PB5
- PA2

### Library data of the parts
CN1 = MCD-00288: Header 10x2, 2mm, RA, TH, Height 3.20mm/3.50mm; Part_Type: Connector; Manufacturer_Part_Number: TMM-110-01-L-D-RA; Manufacturer: SAMTEC; Provided_By: SUBCO
SB8 SB9 SB11 SB13 SB16 SB18 SB21 = MCD-01618: as SB10 on sheet STM32WB1M
SB12 SB14 SB15 SB17 SB19 = MCD-02162: as SB2 on sheet Board_supply

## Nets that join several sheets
3V3: Mems (C4.2 SB5.1 SB6.1 U3.8), STM32WB1M (R2.2 R3.2), Board_supply (7 pins)
3V3_MEMs: Mems (11 pins), Board_supply (SB1.2)
5V: Board_supply (6 pins), STMOD+_interface (CN1.6 CN1.15)
GND: Mems (16 pins), STM32WB1M (70 pins), Board_supply (13 pins), STMOD+_interface (CN1.5 CN1.16)
VDD: STM32WB1M (6 pins), Board_supply (JP1.2)
I2C1_SCL: Mems (U2.13 U3.6 U6.1), STM32WB1M (R3.1 U5.27), STMOD+_interface (SB9.1)
I2C1_SDA: Mems (U2.14 U3.5 U6.6), STM32WB1M (R2.1 U5.25), STMOD+_interface (SB8.1)
NRST: STM32WB1M (5 pins), Board_supply (CN3.12), STMOD+_interface (SB21.2)
PA0: Mems (U6.2), STM32WB1M (U5.37)
PA1: STM32WB1M (U5.11), STMOD+_interface (SB15.2)
PA2: STM32WB1M (U5.13), STMOD+_interface (CN1.20)
PA3: STM32WB1M (U5.28), STMOD+_interface (CN1.13)
PA4: STM32WB1M (U5.9), STMOD+_interface (SB16.1)
PA5: STM32WB1M (U5.39), STMOD+_interface (SB11.1)
PA6: STM32WB1M (U5.12), STMOD+_interface (SB13.1)
PA7: STM32WB1M (U5.29), STMOD+_interface (SB18.1)
PA8: Mems (U2.4), STM32WB1M (U5.10), STMOD+_interface (CN1.14)
PA9-TX: STM32WB1M (SB10.2 U5.38), STMOD+_interface (SB14.1)
PA10-RX: STM32WB1M (SB20.2 U5.36), STMOD+_interface (SB19.1)
PA11: STM32WB1M (U5.32), STMOD+_interface (SB12.1)
PA12: STM32WB1M (U5.30), STMOD+_interface (SB17.1)
PA13-SWDIO: STM32WB1M (U5.35), Board_supply (CN3.4 U4.5)
PA14-SWCLK: STM32WB1M (U5.34), Board_supply (CN3.6 U4.4)
PB2: STM32WB1M (C7.2 R6.1), STMOD+_interface (CN1.17)
PB4: STM32WB1M (U5.33), STMOD+_interface (CN1.19)
PB5: STM32WB1M (U5.26), STMOD+_interface (CN1.18)
PB8: STM32WB1M (U5.14), STMOD+_interface (CN1.11)
VCP_RX: STM32WB1M (SB20.1), Board_supply (CN3.13 U4.1)
VCP_TX: STM32WB1M (SB10.1), Board_supply (CN3.14 U4.3)

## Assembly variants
WB1M: not fitted C6 C7 CN2 R1 R3 R4 R11 SB1 SB3 SB6 SB7 SB9 SB14 SB16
